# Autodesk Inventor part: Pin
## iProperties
Shininess: 64.0
Length Units: 11269
Angle Units: 11279
Time Units: 11290
Mass Units: 11283
Length Display Precision: 3
Angle Display Precision: 2
Compacted: True
Part Number: Pin
Document SubType Name: Modeling
Created: 2003-08
Designer: FranzK
Manufacturer: Standard
Standards Organization: Custom
Density: 0.0
Volumn: 0.0
Area: 0.0
PropertySet Name: Model Information
Control State: 0
Master: False
Checked Out: False
Author: FranzK
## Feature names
1. Extrusion1
2. Hole1
